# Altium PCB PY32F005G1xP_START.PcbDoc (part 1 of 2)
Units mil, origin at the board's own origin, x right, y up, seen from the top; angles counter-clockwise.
Board outline 1771.65 x 3929.06 mil, 2 copper layers (Top Layer, Bottom Layer), stack 21 mil thick; 129 components, 121 nets, 506 pads, 279 vias.
Unrouted connection lines stored in the file: 5.
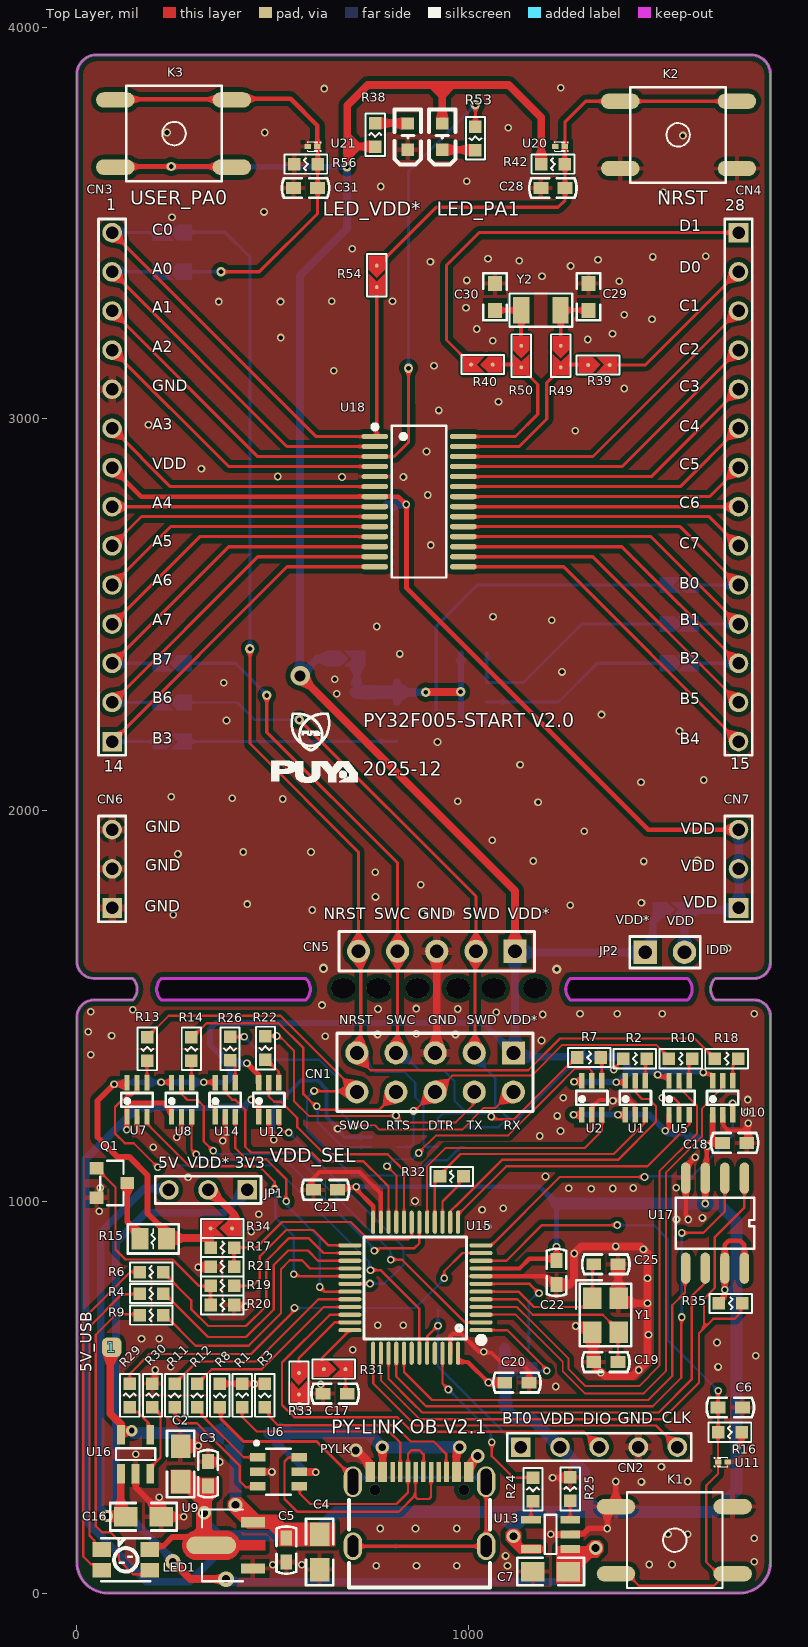
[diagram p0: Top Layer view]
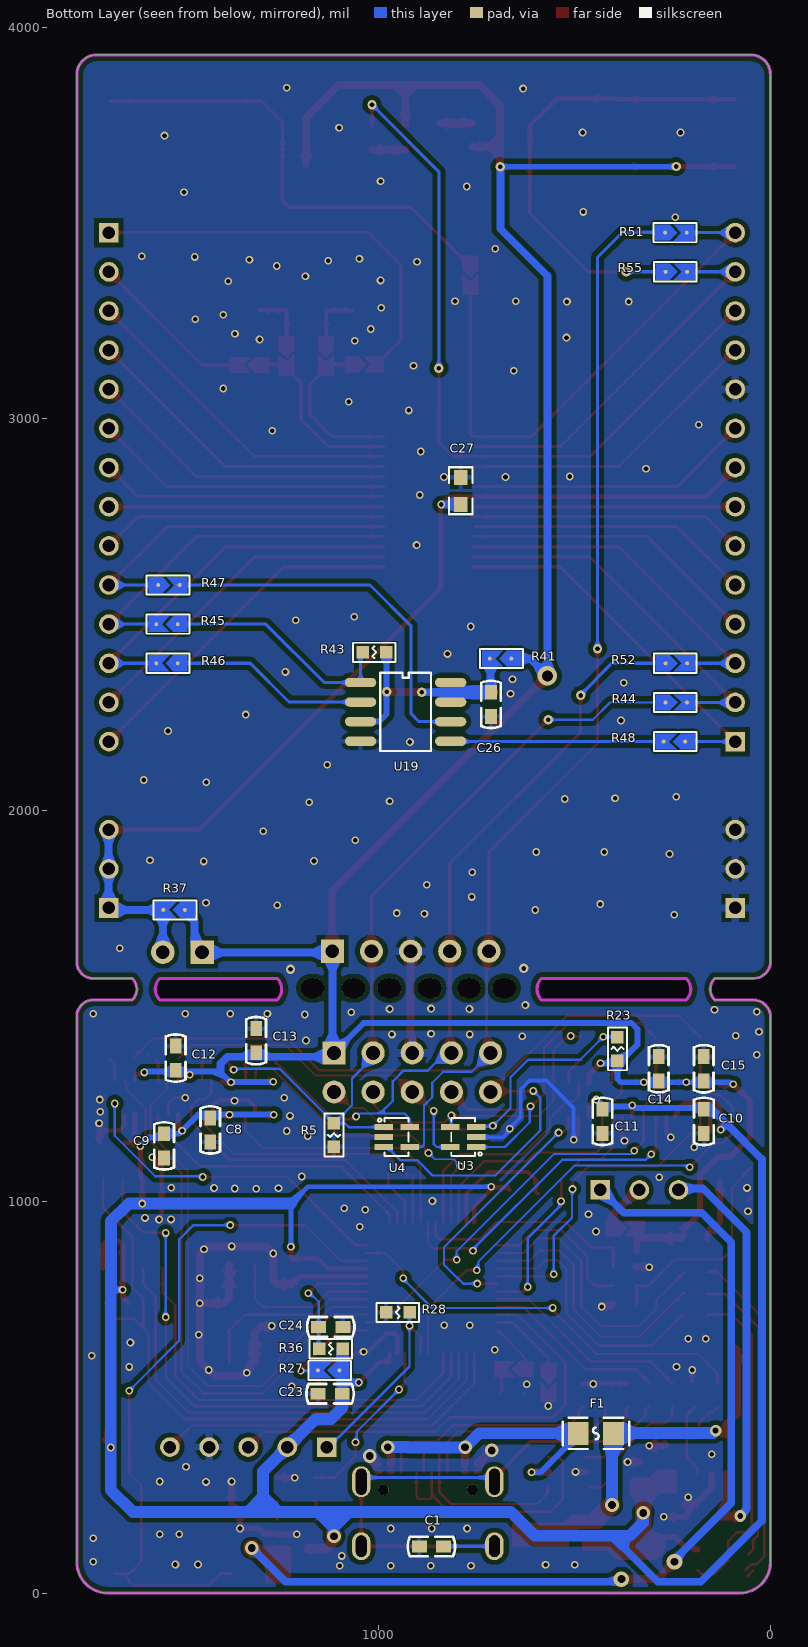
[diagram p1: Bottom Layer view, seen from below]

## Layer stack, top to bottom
Top Solder: solder mask 0.4, Solder Resist, Dk 3.5
Top Layer: signal copper 1.4
Dielectric 2: prepreg 2.8, Composite dielectric, Dk 4.1
Dielectric 1: prepreg 12.6, Composite dielectric, Dk 4.1
Dielectric 3: prepreg 2.8, Composite dielectric, Dk 4.1
Bottom Layer: signal copper 1.4
Bottom Solder: solder mask 0.4, Solder Resist, Dk 3.5

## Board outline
0,78.74 0,1470 cw(c43.75,1471.25) 42.5,1515 142.5,1515 ccw(c115,1542.5) 142.5,1570 42.5,1570 cw(c43.75,1613.75) 0,1615 0,3879.06 cw(c50,3879.06) 50,3929.06 1721.65,3929.06 cw(c1721.65,3879.06) 1771.65,3879.06 1771.65,1611.65 cw(c1730,1611.65) 1730,1570 1630,1570 ccw(c1657.5,1542.5) 1630,1515 1730,1515 cw(c1730,1473.35) 1771.65,1473.35 1771.65,78.74 cw(c1692.91,78.74) 1692.91,0 78.74,0 cw(c78.74,78.74)
cut-out: 1260,1515 cw(c1287.5,1542.5) 1260,1570 1560,1570 cw(c1532.5,1542.5) 1560,1515
cut-out: 215,1515 cw(c242.5,1542.5) 215,1570 585,1570 cw(c557.5,1542.5) 585,1515
cut-out: 215,1515 cw(c242.5,1542.5) 215,1570 585,1570 cw(c557.5,1542.5) 585,1515 565,1515
cut-out: 1260,1515 cw(c1287.5,1542.5) 1260,1570 1560,1570 cw(c1532.5,1542.5) 1560,1515

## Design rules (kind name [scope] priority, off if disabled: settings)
Clearance polygon [InPolygon] p1: gap=12 ignorepadtopadclearanceinfootprint=TRUE
Clearance [All] p2: gap=7 ignorepadtopadclearanceinfootprint=TRUE
HoleToHoleClearance [All] p1: gap=1 allowstackedmicrovias=TRUE
MinimumSolderMaskSliver [All] p1: minsoldermaskwidth=0
PlaneClearance [All] p1: clearance=8
PlaneConnect [All] p1: planeconnectstyle=Direct reliefexpansion=20 reliefentries=4 reliefconductorwidth=10 reliefairgap=10
PolygonConnect [All] p1: thpad.connectstyle=Relief thpad.reliefconductorwidth=20 thpad.reliefentries=4 thpad.polygonreliefangle="90 Angle" thpad.airgapwidth=10 smdpad.connectstyle=Relief smdpad.reliefconductorwidth=12 smdpad.reliefentries=4 smdpad.polygonreliefangle="90 Angle" smdpad.airgapwidth=10 via.connectstyle=Direct via.reliefconductorwidth=10 via.reliefentries=4 via.polygonreliefangle="90 Angle" via.airgapwidth=10
RoutingVias [All] p1: holewidth=28 width=50 viastyle="Through Hole" minholewidth=28 minwidth=50 maxholewidth=28 maxwidth=50
SilkToSilkClearance [All] p1: silktosilkclearance=0
SilkToSolderMaskClearance [IsPad] p1: minsilkscreentomaskgap=0 clearancetoexposedcopper=TRUE
SolderMaskExpansion [All] p1: expansion=4 istentingtop=FALSE
UnRoutedNet [All] p1: checkbadconnections=TRUE
Width [All] p1: maxlimit=100 minlimit=5 preferedwidth=8
23 further rules are at their usual default settings.

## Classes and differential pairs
component class PY32F005G1xS_START: 3 C0 C26 C27 C28 C29 C30 C31 CN3 CN4 CN5 CN6 CN7 JP2 K2 K3 LED_PA1 LED_VDD* R37 R38 R39 R40 R41 R42 R43 R44 R45 R46 R47 R48 R49 R50 R51 R52 R53 R54 R55 R56 U18 U19 U20 U21 Y2
component class PY32F403C1xT_LINK: 1 C1 C2 C3 C4 C5 C6 C7 C8 C9 C10 C11 C12 C13 C14 C15 C16 C17 C18 C19 C20 C21 C22 C23 C24 C25 CN1 CN2 F1 JP1 K1 LED1 PYLK Q1 R1 R2 R3 R4 R5 R6 R7 R8 R9 R10 R11 R12 R13 R14 R15 R16 R17 R18 R19 R20 R21 R22 R23 R24 R25 R26 R27 R28 R29 R30 R31 R32 R33 R34 R35 R36 U1 U2 U3 U4 U5 U6 U7 U8 U9 U10 U11 U12 U13 U14 U15 U16 U17 Y1

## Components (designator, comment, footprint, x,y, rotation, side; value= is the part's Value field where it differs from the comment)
1 "TP_SIN" TP_SIN 89.02,627.93 r90 top
C1 "4.7nF" C0603 866,119 r180 bottom
C2 "10uF" C0805 265,330 r270 top
C3 "100nF" C0603 335,305 r270 top
C4 "10uF" C0805 620,105 r90 top
C5 "100nF" C0603 535,110 r90 top
C6 "100nF" C0603 1669,474 r180 top
C7 "10uF" C0805 1210,55 r0 top
C8 "100nF" C0603 1431,1183 r90 bottom value=104
C9 "100nF" C0603 1548.9,1142.3 r90 bottom value=104
C10 "100nF" C0603 170.2,1204.9 r90 bottom value=104
C11 "100nF" C0603 429,1204.9 r90 bottom value=104
C12 "100nF" C0603 1519.4,1366.6 r270 bottom value=104
C13 "100nF" C0603 1313.8,1411.1 r270 bottom value=104
C14 "100nF" C0603 285.5,1339.2 r270 bottom value=104
C15 "100nF" C0603 170.5,1339.2 r270 bottom value=104
C16 "10uF" C0805 170,195 r180 top
C17 "100nF" C0603 659.59,509.5 r0 top
C18 "100nF" C0603 1680,1150 r180 top value=104
C19 "22pF" C0603 1351.12,590 r0 top
C20 "100nF" C0603 1123.87,537.59 r180 top value=104
C21 "100nF" C0603 635,1030 r0 top value=104
C22 "100nF" C0603 1225.12,819 r90 top value=104
C23 "100nF" C0603 1125,509 r180 bottom value=104
C24 "100nF" C0603 1123.12,680 r0 bottom value=104
C25 "22pF" C0603 1351.12,840 r180 top
C26 "100nF" C0603 714,2270 r90 bottom value=104
C27 "0.1uF/50V" 0603C 791,2815.5 r270 bottom value=2.2uF
C28 "100nF" C0603 1216,3589 r0 top
C29 "22pF" 0603C 1307,3311 r270 top
C30 "22pF" 0603C 1068,3311 r90 top
C31 "100nF" C0603 584,3589 r0 top
CN1 "2X5P" HDR2X5 1115,1380 r180 top
CN2 "CON5" CON5 1134,373 r0 top
CN3 "CON14" CON14 90,2175 r90 top
CN4 "CON14" CON14 1690,3475 r270 top
CN5 "Header 5" HDR1X5 1119.26,1639.56 r180 top
CN6 "CON3" CON3 90,1750 r90 top
CN7 "CON3" CON3 1690,1750 r90 top
F1 "JK-SMD0805-050-16V" F0805 446,408 r180 bottom
JP1 "CON3" CON3 435,1030 r180 top
JP2 "CON2" CON2 1452,1637 r0 top
K1 "TS-KG02S-AT43F" SW-SMD_4P-L6.0-W6.0-P4.50-LS8.5 1528,135 r180 top
K2 "TS-KG02S-AT43F" SW-SMD_4P-L6.0-W6.0-P4.50-LS8.5 1535,3725 r0 top
K3 "TS-KG02S-AT43F" SW-SMD_4P-L6.0-W6.0-P4.50-LS8.5 249,3728 r180 top
LED1 "MHPA3528RGBCT" LED-ARRAY-SMD_4P-L3.5-W2.8-TL 125,85 r0 top
LED_PA1 "GREEN" 0603_LED 934,3735 r90 top
LED_VDD* "RED" 0603_LED 846,3735 r90 top
PYLK "KH-TYPE-C-16P" USB-C-SMD_KH-TYPE-C-16P 875.2,214.81 r0 top locked
Q1 "2302" SOT23 89.37,1047.4 r90 top value=SI2302
R1 "5.1K" R0603 422.49,504.99 r270 top
R2 "27R" R0603 1425.21,1365 r180 top
R3 "5.1K" R0603 480,505 r90 top
R4 "680R" R0603 190,765 r0 top
R5 "1M" R0603 1115,1170 r90 bottom
R6 "680R" R0603 190,820 r0 top
R7 "27R" R0603 1308.39,1368.1 r180 top
R8 "1M" R0603 365,505 r90 top
R9 "680R" R0603 190,710 r0 top
R10 "27R" R0603 1542.35,1365 r180 top
R11 "27R" R0603 250,505 r90 top
R12 "27R" R0603 307.5,505 r90 top
R13 "27R" R0603 179.66,1390.08 r90 top
R14 "27R" R0603 292.3,1390.1 r90 top
R15 "100R" R0805 195,905 r0 top
R16 "10K" R0603 1668,411 r0 top
R17 "20K" R0603 371.52,882.61 r180 top
R18 "27R" R0603 1659.49,1365 r180 top
R19 "100R" R0603 371.53,784.78 r0 top
R20 "100K" R0603 371.52,735.88 r180 top
R21 "10K" R0603 371.53,833.69 r0 top
R22 "27R" R0603 481.63,1392.11 r90 top
R23 "4.7K" R0603 391,1390 r270 bottom
R24 "4.7K" R0603 1165,265 r270 top
R25 "16K" R0603 1260,266 r270 top
R26 "27R" R0603 391.2,1390.7 r90 top
R27 "0R" JP2_SMD 1126,569 r180 bottom
R28 "10K" R0603 952,717.08 r0 bottom
R29 "4.7K" R0603 135,505 r270 top
R30 "16K" R0603 193,505 r270 top
R31 "0R" JP2_SMD 656,572 r180 top
R32 "680R" R0603 957.46,1064.37 r0 top
R33 "0R" JP2_SMD 566.96,537.4 r90 top
R34 "0R" JP2_SMD 371.52,931.52 r0 top
R35 "100K" R0603 1670,740 r180 top
R36 "10K" R0603 1123,624 r180 bottom
R37 "0R" JP2_SMD 1521,1745 r180 bottom
R38 "680R" R0603 762,3724.89 r270 top
R39 "0R" JP2_SMD 1331,3137 r180 top
R40 "0R" JP2_SMD 1037,3138 r0 top
R41 "0R/NC" JP2_SMD 687,2387 r180 bottom
R42 "10K" R0603 1216,3650 r0 top
R43 "100K" R0603 1012,2403 r180 bottom
R44 "100R" JP2_SMD 243,2275 r0 bottom
R45 "0R/NC" JP2_SMD 1538.99,2475 r180 bottom
R46 "0R/NC" JP2_SMD 1538.99,2375 r180 bottom
R47 "0R/NC" JP2_SMD 1539,2575 r0 bottom
R48 "0R/NC" JP2_SMD 242.99,2175 r180 bottom
R49 "0R" JP2_SMD 1236,3161.01 r90 top
R50 "0R" JP2_SMD 1135,3161.01 r90 top
R51 "0R" JP2_SMD 244,3475 r0 bottom
R52 "100R" JP2_SMD 243,2375 r0 bottom
R53 "680R" R0603 1018,3716 r90 top
R54 "0R" JP2_SMD 766,3366 r90 top
R55 "0R" JP2_SMD 243,3375 r0 bottom
R56 "1.5K" R0603 585,3650 r0 top
U1 "74LVC1T45DW" SOT363 1426.64,1265 r0 top
U2 "74LVC1T45DW" SOT363 1315.21,1265 r0 top
U3 "ESD_6V1" ESD_SOT323-5L 785,1165 r90 bottom value=ESDALC6V1W5
U4 "ESD_6V1" ESD_SOT323-5L 955,1165 r270 bottom value=ESDALC6V1W5
U5 "74LVC1T45DW" SOT363 1538.06,1265 r0 top locked
U6 "USBLC6-2SC6" SOT23-6 515,310 r90 top
U7 "74LVC1T45DW" SOT363 153.55,1260 r0 top locked
U8 "74LVC1T45DW" SOT363 267.26,1260 r0 top
U9 "LM1117F-3.3" SOT-89-3_L4.5-W2.5-P1.50-LS4.2-BR 396.39,122.01 r0 top
U10 "74LVC1T45DW" SOT363 1649.49,1265 r0 top
U11 "ESDALC6V1-1U2" ESD_ST0201 1650,335 r0 top
U12 "74LVC1T45DW" SOT363 490.12,1260 r0 top
U13 "MT9700" SOT23-5 1210,150 r90 top
U14 "74LVC1T45DW" SOT363 378.69,1260 r0 top
U15 "PY32F403C1xT" LQFP-48_L7.0-W7.0-P0.50-LS9.0-BL 865,780 r90 top locked
U16 "MT9700" SOT23-5 150,355 r0 top
U17 "P25Q64SH" SOP-8P 1630,945 r180 top value=SST25VF020B
U18 "PY32F005G1xP7" TSSOP-28_L9.7-W4.4-P0.65-LS6.4-BL 874,2788 r270 top locked
U19 "P25Q64SH" SOP-8P 932,2251 r270 bottom value=SST25VF020B
U20 "ESDALC6V1-1U2" ESD_ST0201 1234,3695 r180 top
U21 "ESDALC6V1-1U2" ESD_ST0201 602,3695 r180 top
Y1 "24MHz" CRYSTAL-SMD_4P-L3.2-W2.5-BL 1350.12,710 r270 top
Y2 "32.768KHz" CRYSTAL-SMD_L3.2-W1.5-1 1185,3277 r180 top value=X503225MSB2GI

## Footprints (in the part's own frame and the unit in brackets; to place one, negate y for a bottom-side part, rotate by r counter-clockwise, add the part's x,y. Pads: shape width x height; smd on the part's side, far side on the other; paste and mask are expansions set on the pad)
0603_LED [mil]
  rect 31.5x31.5 smd: 1(19,1) 2(-48,1)
  silkscreen extent -86,-33 55,35
0603C [mil]
  rect 38x35 smd: 1(-34.5,0) 2(34.5,0)
  silkscreen extent -60,-30 60,30, body extent -31,-16 32,16, height 12
C0603 [mil]
  rect 38x30 smd: 1(-31,0) 2(31,0)
  silkscreen extent -60,-25 60,25
C0805 [mil]
  rect 60x50 smd: 1(-45,0) 2(45,0)
  silkscreen extent -85,-35 85,35
CON2 [mil]
  rect 60x60 hole 35: 1(0,0)
  round 60 hole 35: 2(100,0)
  silkscreen extent -40,-40 140,40
CON3 [mil]
  rect 50x50 hole 32: 1(0,0)
  round 50 hole 32: 2(100,0) 3(200,0)
  silkscreen extent -35,-35 235,35
CON5 [mil]
  rect 50x50 hole 32: 1(0,0)
  round 50 hole 32: 2(100,0) 3(200,0) 4(300,0) 5(400,0)
  silkscreen extent -35,-35 435,35
CON14 [mil]
  rect 50x50 hole 32: 1(0,0)
  round 50 hole 32: 2(100,0) 3(200,0) 4(300,0) 5(400,0) 6(500,0) 7(600,0) 8(700,0) 9(800,0) 10(900,0) 11(1000,0) 12(1100,0) 13(1200,0) 14(1300,0)
  silkscreen extent -35,-35 1335,35
CRYSTAL-SMD_4P-L3.2-W2.5-BL [mm]
  rect 1.4x1.2 smd: 1(-1.1,-0.85) 2(1.1,-0.85) 3(1.1,0.85) 4(-1.1,0.85)
  silkscreen extent -2.26,-1.91 2.03,1.68
CRYSTAL-SMD_L3.2-W1.5-1 [mm]
  rect 1.05x1.7 smd: 1(-1.275,0) 2(1.275,0)
  silkscreen extent -2.03,-1.08 2.03,1.08
ESD_SOT323-5L [mm]
  rect 0.4x1.2 smd mask+0.05: 1(-0.65,-0.85) 2(0,-0.85) 3(0.65,-0.85) 4(0.65,0.85) 5(-0.65,0.85)
  silkscreen extent -1.23,-1.21 1.23,0.77, body extent -1.15,-1.05 1.15,1.05, height 1.1
ESD_ST0201 [mm]
  rect 0.425x0.33 smd mask+0.05: 1(-0.312,0) 2(0.312,0)
  silkscreen extent -0.55,-0.3 0.33,0.3, body extent -0.34,-0.18 0.34,0.18, height 0.34
F0805 [mm]
  rect 1.335x1.5 smd paste-100 mask+0.051: 1(-1.142,0) 2(1.142,0)
  silkscreen extent -2.16,-1.02 2.16,1.02
HDR1X5 [mm] "Connector; Header; 5 Position"
  rect 1.5x1.5 hole 0.9: 1(0,0)
  round 1.5 hole 0.9: 2(2.54,0) 3(5.08,0) 4(7.62,0) 5(10.16,0)
  silkscreen extent -1.27,-1.27 11.43,1.27
HDR2X5 [mm] "Connector; Header; 4x2 Position"
  rect 1.5x1.5 hole 0.9: 1(0,0)
  round 1.5 hole 0.9: 2(0,2.54) 3(2.54,0) 4(2.54,2.54) 5(5.08,0) 6(5.08,2.54) 7(7.62,0) 8(7.62,2.54) 9(10.16,0) 10(10.16,2.54)
  silkscreen extent -1.27,-1.27 11.43,3.81
JP2_SMD [mil]
  round 1 smd: 1(21.75,0) 2(-23.03,0.03)
  round 10 smd paste-393.7: 1(25,0) 2(-30,0)
  Top Layer region: -6.25,0 13.75,20 49.75,20 49.75,-20 49.75,-20 13.75,-20
  Top Layer region: -49.77,20.03 -49.77,20.03 3.72,20.03 -16.28,0.03 3.72,-19.98 -49.78,-19.98 -49.78,-19.98
  silkscreen extent -55,-25 54,25
LED-ARRAY-SMD_4P-L3.5-W2.8-TL [mm]
  rect 1.2x0.95 smd: 1(1.55,0.665) 2(1.55,-0.665) 3(-1.55,-0.665) 4(-1.55,0.665)
  silkscreen extent -1.6,-1.4 1.6,1.4
LQFP-48_L7.0-W7.0-P0.50-LS9.0-BL [mm]
  oval 0.27x1.5 smd mask+0.05: 1(-2.75,-4.25) 2(-2.25,-4.25) 3(-1.75,-4.25) 4(-1.25,-4.25) 5(-0.75,-4.25) 6(-0.25,-4.25) 7(0.25,-4.25) 8(0.75,-4.25) 9(1.25,-4.25) 10(1.75,-4.25) 11(2.25,-4.25) 12(2.75,-4.25) 25(2.75,4.25) 26(2.25,4.25) 27(1.75,4.25) 28(1.25,4.25) 29(0.75,4.25) 30(0.25,4.25) 31(-0.25,4.25) 32(-0.75,4.25) 33(-1.25,4.25) 34(-1.75,4.25) 35(-2.25,4.25) 36(-2.75,4.25)
  oval 1.5x0.27 smd mask+0.05: 13(4.25,-2.75) 14(4.25,-2.25) 15(4.25,-1.75) 16(4.25,-1.25) 17(4.25,-0.75) 18(4.25,-0.25) 19(4.25,0.25) 20(4.25,0.75) 21(4.25,1.25) 22(4.25,1.75) 23(4.25,2.25) 24(4.25,2.75) 37(-4.25,2.75) 38(-4.25,2.25) 39(-4.25,1.75) 40(-4.25,1.25) 41(-4.25,0.75) 42(-4.25,0.25) 43(-4.25,-0.25) 44(-4.25,-0.75) 45(-4.25,-1.25) 46(-4.25,-1.75) 47(-4.25,-2.25) 48(-4.25,-2.75)
  silkscreen extent -3.59,-4.46 3.3,3.34
R0603 [mil]
  rect 32x32 smd: 1(-30,0) 2(30,0)
  silkscreen extent -55,-25 55,25
R0805 [mm]
  rect 1.1x1.4 smd: 1(-0.85,0) 2(0.85,0)
  silkscreen extent -1.65,-0.95 1.65,0.95
SOP-8P [mil]
  oval 24x80 smd: 1(-75,-115) 2(-25,-115) 3(25,-115) 4(75,-115) 5(75,115) 6(25,115) 7(-25,115) 8(-75,115)
  silkscreen extent -100,-65 100,65
SOT23 [mm]
  rect 0.8x0.9 smd: 1(0.95,1) 2(-0.95,1) 3(0,-1)
  silkscreen extent -1.45,-0.75 1.45,0.75
SOT23-5 [mil]
  rect 20x50 smd: 1(-37.5,-50) 2(0,-50) 3(37.5,-50) 4(37.5,50) 5(-37.5,50)
  silkscreen extent -50,-15 50,15
SOT23-6 [mm]
  rect 0.55x1 smd: 1(0.95,1.35) 2(0,1.35) 3(-0.95,1.35) 4(-0.95,-1.35) 5(0,-1.35) 6(0.95,-1.35)
  silkscreen extent -1.5,-0.8 1.96,1.52
SOT363 [mm]
  rect 0.35x1 smd: 1(-0.65,-1.1) 2(0,-1.1) 3(0.65,-1.1) 4(0.65,1.1) 5(0,1.1) 6(-0.65,1.1)
  silkscreen extent -1.02,-0.45 1.02,0.45, body extent -1,-1.1 1,1.16, height 1
SOT-89-3_L4.5-W2.5-P1.50-LS4.2-BR [mm]
  rect 1.575x0.672 smd: 1(1.356,-1.5) 3(1.356,1.5)
  oval 3.226x1.14 smd: 2(-1.356,0)
  Top Layer region: -2.283,0.95 -0.429,0.95 -0.384,0.949 -0.34,0.946 -0.296,0.94 -0.252,0.933 -0.208,0.924 -0.165,0.912 -0.123,0.899 -0.081,0.884 -0.04,0.866 0,0.847 0.04,0.826 0.078,0.803 0.115,0.779 0.151,0.752 0.185,0.724 0.219,0.695 0.251,0.664 0.281,0.631 0.31,0.597 0.337,0.562 0.362,0.525 0.386,0.488 0.408,0.449 0.428,0.409 0.447,0.33 2.144,0.33 2.144,-0.33 0.447,-0.33 0.428,-0.409 0.408,-0.449 0.386,-0.488 0.362,-0.526 0.337,-0.562 0.31,-0.597 0.281,-0.631 0.251,-0.664 0.219,-0.695 0.185,-0.725 0.151,-0.753 0.115,-0.779 0.078,-0.804 0.04,-0.827 0,-0.848 -0.04,-0.867 -0.081,-0.884 -0.123,-0.899 -0.165,-0.913 -0.208,-0.924 -0.252,-0.934 -0.296,-0.941 -0.34,-0.946 -0.384,-0.949 -0.429,-0.95 -2.283,-0.95 -2.328,-0.949 -2.372,-0.946 -2.416,-0.941 -2.46,-0.934 -2.504,-0.924 -2.547,-0.913 -2.589,-0.899 -2.631,-0.884 -2.672,-0.867 -2.713,-0.848 -2.752,-0.827 -2.79,-0.804 -2.827,-0.779 -2.863,-0.753 -2.898,-0.725 -2.931,-0.695 -2.963,-0.664 -2.993,-0.631 -3.022,-0.597 -3.049,-0.562 -3.075,-0.526 -3.098,-0.488 -3.12,-0.449 -3.141,-0.409 -3.159,-0.369 -3.175,-0.327 -3.189,-0.285 -3.202,-0.242 -3.212,-0.199 -3.22,-0.155 -3.227,-0.111 -3.231,-0.067 -3.233,-0.022 -3.233,0.022 -3.231,0.067 -3.227,0.111 -3.22,0.155 -3.212,0.199 -3.202,0.242 -3.189,0.285 -3.175,0.327 -3.159,0.369 -3.141,0.409 -3.12,0.449 -3.098,0.488 -3.075,0.525 -3.049,0.562 -3.022,0.597 -2.993,0.631 -2.963,0.664 -2.931,0.695 -2.898,0.724 -2.863,0.752 -2.827,0.779 -2.79,0.803 -2.752,0.826 -2.713,0.847 -2.672,0.866 -2.631,0.884 -2.589,0.899 -2.547,0.912 -2.504,0.924 -2.46,0.933 -2.416,0.94 -2.372,0.946 -2.328,0.949 -2.283,0.95
  silkscreen extent -1.95,-2.33 0.7,2.33
SW-SMD_4P-L6.0-W6.0-P4.50-LS8.5 [mm]
  oval 2.5x1 smd: 1(-3.734,2.177) 2(3.835,2.177) 3(-3.734,-2.184) 4(3.835,-2.184)
  silkscreen extent -3.08,-3.1 3.12,3.09, body extent -4.48,-3 4.52,3, height 8.95
TP_SIN [mil]
  rrect60% 50x50 smd: 1(0,0)
TSSOP-28_L9.7-W4.4-P0.65-LS6.4-BL [mm]
  oval 0.343x1.731 smd paste+0 mask+0.051: 1(-4.225,-2.866) 2(-3.575,-2.866) 3(-2.925,-2.866) 4(-2.275,-2.866) 5(-1.625,-2.866) 6(-0.975,-2.866) 7(-0.325,-2.866) 8(0.325,-2.866) 9(0.975,-2.866) 10(1.625,-2.866) 11(2.275,-2.866) 12(2.925,-2.866) 13(3.575,-2.866) 14(4.225,-2.866) 15(4.225,2.866) 16(3.575,2.866) 17(2.925,2.866) 18(2.275,2.866) 19(1.625,2.866) 20(0.975,2.866) 21(0.325,2.866) 22(-0.325,2.866) 23(-0.975,2.866) 24(-1.625,2.866) 25(-2.275,2.866) 26(-2.925,2.866) 27(-3.575,2.866) 28(-4.225,2.866)
  silkscreen extent -5,-3.02 4.93,1.77
USB-C-SMD_KH-TYPE-C-16P [mm]
  oval 1.2x2 hole 0.7 slot 1.7 at 90 deg: 1(-4.32,1.765) 2(4.32,1.765)
  oval 1.2x1.8 hole 0.7 slot 1.4 at 90 deg: 3(-4.32,-2.415) 4(4.32,-2.415)
  rect 0.3x1.3 smd: A1(-3.35,2.415) A4(-2.55,2.415) A5(-1.25,2.415) A6(-0.25,2.415) A7(0.25,2.415) A8(1.25,2.415) A9(2.55,2.415) A12(3.35,2.415) B1(3.05,2.415) B4(2.25,2.415) B5(1.75,2.415) B6(0.75,2.415) B7(-0.75,2.415) B8(-1.75,2.415) B9(-2.25,2.415) B12(-3.05,2.415)
  round 0.7 hole 0.7 unplated: ""(-2.89,1.235) ""(2.89,1.235)
  silkscreen extent -4.57,-5.08 4.57,0.57

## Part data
C1 C3 C5 C6 C17 C19 C25 C28 C31: library part C0603
C2 C4 C7 C16: library part C0805
C8 C9 C10 C11 C12 C13 C14 C15 C18 C20 C21 C22 C23 C24 C26: library part 贴片高压陶瓷电容, "Capacitor (Semiconductor SIM Model)"
C27: library part CAP, "Capacitor"
C29 C30: library part Cap, "Capacitor"
CN1: Color=黑色, Current Rating (Max)=-, JLCPCB Part Class="Extended Part", LCSC Part Name="间距:2.54mm 2x5P 直插 方针", Manufacturer=XFCN(兴飞), Manufacturer Part=PZ254V-12-10P, Operating Temperature Range=-40℃~+105℃
CN5: "Header, 5-Pin"
F1: Current - Max=100A, Hold Current=500mA, JLCPCB Part Class="Extended Part", LCSC Part Name="6V 0.5A 贴片自恢复", Manufacturer=JK(金科), Operating Temperature=-40℃~+85℃, Power Dissipation=600mW, Resistance - Initial (Ri) (Min)=150mΩ, Resistance - Post Trip (R1) (Max)=850mΩ, Trip Current=1A, Voltage - Max=6V
JP2: library part CON2_DIP
K1 K2 K3: Actuator/Cap Color=黑色, Contact Current=50mA, Insulation Resistance=100MΩ, JLCPCB Part Class=扩展库, LCSC Part Name="6*6*4.3mm 立贴 轻触开关", Manufacturer=HANBO(汉博), Operating Force=250gf, Voltage Rating (DC)=12V
LED1: JLCPCB Part Class=扩展库, LCSC Part Name=RGB三色, Manufacturer=MEIHUA(美华)
LED_PA1 LED_VDD*: library part PDI-E803_Dup1
PYLK: BOM_JLCPCB Part Class="Extended Part", BOM_Manufacturer="Shenzhen Kinghelm Elec"
Q1: library part "MOSFET N", "MOSFET N"
R1 R2 R3 R4 R5 R6 R7 R8 R9 R10 R11 R12 R13 R14 R16 R17 R18 R19 R20 R21 R22 R23 R24 R26 R27 R28 R29 R31 R32 R33 R34 R35 R36 R37 R38 R39 R40 R41 R42 R43 R44 R45 R46 R47 R48 R49 R50 R51 R52 R53 R54 R55 R56: library part R0603
R15: library part R0805
R25 R30: library part R0603_7, "0603WAF1602T5E 16KΩ(1602) ±1%"
U3 U4: library part ESDALC6V1W5, "Dual Transil array for ESD protection", Manufacturer=STMICROELECTRONICS
U11 U20 U21: "ESD protection 6V1", Manufacturer=STMICROELECTRONICS
U15: "LQFP48", BOM_Manufacturer=PUYA(普冉)
U17 U19: library part SST25VF010, "SST25VF010"
U18: "TSSOP28(9.7*4.4)", BOM_Manufacturer=PUYA(普冉)
Y1: library part ABM8AIG-24.000MHZ-82Z-T, "±20ppm , 12.5pF , T_use: -40°C~125°C", Equivalent Series Resistance (ESR)=50Ω, External load capacitor=8pF, Frequency Stability(Full temperature range)=±50ppm, JLCPCB Part Class="Extended Part", LCSC Part Name="24MHz ±20ppm 8pF", Manufacturer=ABRACON, Normal temperature Frequency Tolerance=±20ppm, Operating Temperature=-40℃~+125℃
Y2: library part CRYSTAL_1, "Crystal"

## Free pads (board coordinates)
  oval 60x50 hole 50 slot 60 at 0 deg unplated: 1(680,1545) 1(770,1545) 1(870,1545) 1(973.55,1545) 1(1065,1545) 1(1170,1545)

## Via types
v1: diameter 19.68, hole 11.81, Top Layer to Bottom Layer, 140 vias
v2: diameter 19.68, hole 11.81, Top Layer to Bottom Layer, tented both sides, 114 vias
v3: diameter 24, hole 12, Top Layer to Bottom Layer, tented both sides, 12 vias
v4: diameter 35, hole 20, Top Layer to Bottom Layer, tented both sides, 8 vias
v5: diameter 30, hole 15, Top Layer to Bottom Layer, tented both sides, 2 vias
v6: diameter 40, hole 20, Top Layer to Bottom Layer, tented both sides, 2 vias
v7: diameter 50, hole 28, Top Layer to Bottom Layer, 1 vias

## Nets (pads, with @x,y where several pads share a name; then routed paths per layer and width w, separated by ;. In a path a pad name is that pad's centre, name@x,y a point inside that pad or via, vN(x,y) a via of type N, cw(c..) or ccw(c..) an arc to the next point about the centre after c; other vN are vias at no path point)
3.3V_OUT_EN: R24.1 U15.46 | length 443
  Top Layer w6: U15.46@933.9,612.68 933.9,535.1 v2(949,520) ; v2(1060,385) 1060,349.4 1114.4,295 R24.1@1165,295
  Bottom Layer w6: v2(949,520) 1056.94,412.06 1056.94,388.06 v2(1060,385)
3V3_PYLK: C2.2 C3.2 C8.2 C9.2 C10.2 C11.2 C18.2 C20.2 C21.2 C22.2 C23.2 CN2.2 LED1.1 R16.2 R27.1 R35.2 R36.2 U1.1 U2.1 U5.1 U7.1 U8.1 U9.2 U10.1 U12.1 U13.5 U14.1 U15.9 U15.24 U15.48 U17.3 U17.7 U17.8 | length 7883.4
  Top Layer w10: v2(445.16,1260.63) 449.42,1260.63 464.53,1245.52 U12.1@464.53,1216.69 ; C21.2@666,1030 C21.2@670.66,1034.66 ; C22.2@1225,854.12 v2(1225,885) ; v2(1685,372) 1698,385 R16.2@1698,411
  Top Layer w11: v2@710,1035 756.73,988.27 U15.24@756.73,947.32 ; U15.48@973.27,612.68 973.27,590.61 973.45,590.42 998.23,590.42 1053.65,535 v2@1055.12,535 ; U15.9@1032.32,829.21 1130.39,829.21 1155.3,854.12 C22.2@1225,854.12
  Top Layer w12: v1(127.35,1183.66) 127.96,1184.27 U7.1@127.96,1216.69 127.96,1237.87 141.96,1251.88 219.81,1251.88 241.67,1230.01 U8.1@241.67,1216.69 ; U14.1@353.1,1216.69 353.99,1217.58 353.12,1218.46 v2(353.12,1246.39) ; C21.2@670.66,1034.66 671.99,1035.99 710.99,1035.99 v2(713.28,1038.28) ; v2(1268.73,1222.03) 1269.06,1221.69 U2.1@1289.62,1221.69 ; v2(1382,1221.9) 1382.21,1221.69 U1.1@1401.05,1221.69 ; v1(1503.01,1181.02) 1512.47,1190.48 U5.1@1512.47,1221.69 1511.58,1220.8 U5.1@1511.8,1220.58 ; v2(1605,995) U17.3@1605,1060 1609.01,1064.01 1609.01,1141.25 v2(1609.87,1142.11) ; 1617.76,1150 C18.2@1649,1150 ; R35.2@1640,740 1655,755 v2(1655,775) U17.7@1655,830 1655,890 1665,900 1695,900 1705,890 U17.8@1705,830
  Top Layer w15: LED1.1@186.02,111.18 193.48,111.18 193.48,111.66 202.14,120.32 221.03,120.32 244.3,143.59 U9.2@313.8,143.59 ; v2(1609.87,1142.11) 1617.76,1150 1623.9,1156.14 U10.1@1623.9,1221.69
  Top Layer w20: v2@1054.87,537.59 C20.2@1092.87,537.59
  Bottom Layer w12: v2(713.28,1038.28) 1181.72,1038.28 1225,995 ; v2(1225,885) 1225,990 ; v2(1655,775) 1684.65,775
  Bottom Layer w15: C10.2@170.2,1235.9 173.64,1239.34 346.07,1239.34 v2(353.12,1246.39) 356.92,1242.6 422.3,1242.6 C11.2@429,1235.9 429,1244.47 v2(445.16,1260.63) v2@443.56,1262.22 ; v2(1268.73,1222.03) 1431,1222.03 1462,1222.03 v1(1503.01,1181.02) 1510.73,1173.3 C9.2@1548.9,1173.3 ; C9.2@1558.32,1163.88 1588.1,1163.88 v2(1609.87,1142.11)
  Bottom Layer w20: v1(127.35,1183.66) 112.87,1198.15 111.65,1198.15 ; C10.2@170.2,1244.2 157.7,1244.2 111.65,1198.15 ; 405.3,146.25 287.88,28.84 178.16,28.84 22,185 22,1108.5 111.65,1198.15 ; v2(1051.39,538) 1089.87,538 1094,533.87
  Bottom Layer w30: v4(325,205) 325.96,204.04 325.96,179.91 359.61,146.25 405.3,146.25 602.14,146.25 663.2,207.32 1115.96,207.32 ; R36.2@1093,624 1093,570 1099.12,563.87 ; 1104.25,574.53 R27.1@1104.25,569 1099.12,563.87 ; v4(1115,145) 1115.96,145.96 1115.96,207.32 ; 1225,995 v2(1605,995) 1638.96,995 1684.65,949.31 1684.65,775 1685,774.65 v2(1685,372) 1685,263.15 1629.17,207.32 1296,207.32 ; 1099.12,563.87 1094,558.75 1094,533.87 C23.2@1094,509 1094.82,509 1094.82,472.18 1122,445 1162,445 CN2.2@1234,373 1296,311 1296,207.32 ; 1115.96,207.32 1296,207.32
3V3_USB_PYLK: C7.2 JP1.1 U13.1 | length 2404.2
  Top Layer w20: v6@245.8,80 290.03,35.77 v6(380.96,35.77)
  Bottom Layer w20: v6(245,80) 245,85.41 100.1,230.31 100.1,895.86 175.6,971.36 374.6,971.36 418.24,1015 420,1015 433.24,1028.24 JP1.1@433.24,1030 ; v6(380.96,35.77) 387.82,28.91 1238.91,28.91 v4(1325,115) v4@1326.78,113.22
5V_OUT_EN: R29.1 U15.11 | length 1065.3
  Top Layer w6: R29.1@135,535 135,560 185.65,610.65 444.42,610.65 555.92,722.16 v2(555.92,728.42) ; v2(938.27,804.07) 938.27,821.87 984.98,868.58 U15.11@1032.32,868.58
  Bottom Layer w6: v2(555.92,728.42) 864.41,728.42 938.27,802.29 v2(938.27,804.07)
5V_USB_CHGR: 1.1 C4.2 C5.2 F1.2 U9.3 U16.5 | length 702.8
  Top Layer w20: 1.1@90,625 85.21,620.21 85.21,458.5 112.5,431.21 U16.5@112.5,405 ; U16.5@112.5,413.09 138.09,413.09 v5(140,415)
  Bottom Layer w30: v5(140,415) 146,409 387.43,409 405,391.43 v4(405,225)
5V_USB_PYLK: C16.2 JP1.3 U16.1 | length 1109.9
  Top Layer w20: v5(77.39,196.82) 78.3,195.91 124.09,195.91 C16.2@125,195 ; U16.1@112.5,304.69 112.5,290 112.19,289.69 112.19,210 C16.2@125,210
  Bottom Layer w20: v5(77.39,196.82) 74.92,197.32 71.21,201.03 69.81,202.43 60.92,215.77 60.92,921.89 172.85,1033.82 231.18,1033.82 JP1.3@235,1030
AD_TVDD: R17.1 R21.2 U15.19 | length 586.3
  Top Layer w6: R21.2@401.52,833.7 R17.1@401.52,882.61 458.79,882.61 523.97,947.79 699.66,947.79 743.59,903.86 846.86,903.86 855.16,912.17 U15.19@855.16,947.32
DIR_RESET: U10.5 U15.3 | length 1394.4
  Top Layer w5: U15.3@1032.32,711.1 1120.66,711.1 1160.03,671.73 1241,590.76 1241,566.99 1297.78,510.22 1448.12,510.22 1504.53,566.63 1504.53,1074.04 1596.97,1166.47 1596.97,1238.45 1645.1,1286.59 1645.1,1303.92 U10.5@1649.49,1308.31
DIR_RTCK_DTR: U5.5 U15.4 | length 1362.6
  Top Layer w5: U15.4@1032.32,730.79 1123.69,730.79 1163.06,691.42 1256,598.48 1256,571.92 1299.09,528.83 1435.95,528.83 1488.53,581.41 1488.53,1078.32 1583.97,1173.76 1583.97,1245.09 1542.45,1286.6 1542.45,1303.92 U5.5@1538.06,1308.31
DIR_TCK_SWCLK: U2.5 U15.21 | length 808
  Top Layer w5: v2(792.12,1090.67) 815.79,1067 U15.21@815.79,947.32 ; v1(873.49,1124.13) 873.49,1125.57 917.33,1169.41 1102.34,1169.41 1216.71,1283.79 1273.38,1340.46 1307.19,1340.46 1315.21,1332.43 U2.5@1315.21,1308.31
  Bottom Layer w5: v2(792.12,1090.67) 809.61,1108.16 857.52,1108.16 v1(873.49,1124.13)
DIR_TDI_VCP_TX: U12.5 U15.20 | length 603.7
  Top Layer w6: U12.5@490.12,1303.31 490.12,1268.77 503.92,1254.98 520.97,1254.98 563.25,1212.7 563.25,1189.92 632.11,1121.06 793.64,1121.06 835.47,1079.24 U15.20@835.47,947.32
DIR_TDO_SWO: U7.5 U15.43 | length 1250.3
  Top Layer w6: U7.5@153.55,1303.31 153.55,1284.73 140.19,1271.38 127.22,1271.38 97.4,1241.56 97.4,1174.28 122.48,1149.2 145.25,1149.2 v1(206.55,1087.9) ; v2(750,825) 775.69,825 874.84,725.85 U15.43@874.84,612.68
  Bottom Layer w5: v1(206.55,1087.9) 211.05,1092.41 500.21,1092.41 746.36,846.25 746.36,828.64 v2(750,825)
DIR_TMS_SWDIO: U1.5 U15.14 | length 784.3
  Top Layer w6: U15.14@953.58,947.32 953.58,973.99 956.95,977.36 956.95,978.29 966.51,987.85 967.44,987.85 1086.13,1106.54 1381.8,1106.54 1479.4,1204.13 1479.4,1243.36 1460.78,1261.98 1443.79,1261.98 1428.52,1277.25 1428.52,1306.42 U1.5@1426.64,1308.31
DIR_TRST_RTS: U8.5 U15.2 | length 1100.7
  Top Layer w6: U8.5@267.26,1303.31 267.85,1302.72 267.85,1274.24 282.53,1259.56 308.14,1259.56 323.94,1243.76 323.94,1153.79 v2(348.06,1129.67) ; v2(801.52,851.68) 830.72,851.68 990.98,691.42 U15.2@1032.32,691.42
  Bottom Layer w5: v2(348.06,1129.67) 356.33,1121.41 553.59,1121.41 801.52,873.48 v2(801.52,851.68)
DIR_VCP_RX: U14.5 U15.22 | length 688.5
  Top Layer w6: U14.5@378.69,1303.31 380.07,1301.93 380.07,1277.14 396.6,1260.6 404.2,1260.6 430,1234.81 430,1140.06 444.61,1125.45 599.3,1125.45 622.05,1102.71 732.18,1102.71 776.38,1058.51 796.1,1038.79 U15.22@796.1,947.32
F_VDD: C26.2 R41.2 R43.2 U19.3 U19.7 U19.8 | length 628.2
  Top Layer w20: v3(891,2301) 891.5,2301.5 979.5,2301.5 v3(980,2302)
  Bottom Layer w15: R43.2@981,2400 981,2245.18 1000.18,2226 U19.3@1047,2226
  Bottom Layer w20: C26.2@715,2304 R41.2@715,2386.53 ; U19.7@817,2276 817.59,2276.59 817.59,2301 ; U19.8@817,2326 817.59,2325.41 817.59,2301 ; v3(891,2301) 817.59,2301
  Bottom Layer w35: C26.2@714,2301 817.59,2301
